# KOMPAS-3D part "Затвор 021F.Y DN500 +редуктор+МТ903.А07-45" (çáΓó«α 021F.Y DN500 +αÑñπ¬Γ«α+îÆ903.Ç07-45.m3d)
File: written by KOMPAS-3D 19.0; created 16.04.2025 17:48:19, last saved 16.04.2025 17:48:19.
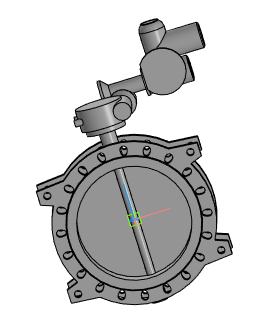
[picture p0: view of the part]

Document properties: Полное имя файла: Затвор 021F.Y DN500 +редуктор+МТ903.А07-45.a3d

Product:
- Part/product: Затвор 021F.Y DN500 +редуктор+МТ903.А07-45
    Масса: 289.315

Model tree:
1. Операция без истории:1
